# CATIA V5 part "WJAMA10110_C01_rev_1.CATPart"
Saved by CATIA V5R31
Part number: WJAMA10110_C01_rev_1
Source: Unknown
Bounding box of the stored display mesh (mm): x 4119.118 to 4134.35, y 478.04 to 529.845, z 632.99 to 657.593
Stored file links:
  \\solize.local\damia\dept\DDE_Design\10_order\2305701_JAMA_変換検証STEP3_お手本モデル作成\work\02_マツダ_板金\10_CATIA_V5\231211\WJAMA10110_C01_rev_1.CATPart
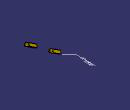
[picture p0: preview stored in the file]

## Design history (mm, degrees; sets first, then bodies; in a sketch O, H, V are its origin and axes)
TTRSSet1
f4a2d38f3ddc11d3a929006094b99c4b_11 "CATTPSSet"
Body1 "MANIFOLD_SOLID_BREP #9747" (main body)
  Solid1: solid without history
Body2 "MANIFOLD_SOLID_BREP #9748"
  Solid2: solid without history
Body3 "MANIFOLD_SOLID_BREP #9749"
  Solid3: solid without history
Body4 "MANIFOLD_SOLID_BREP #9750"
  Solid4: solid without history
